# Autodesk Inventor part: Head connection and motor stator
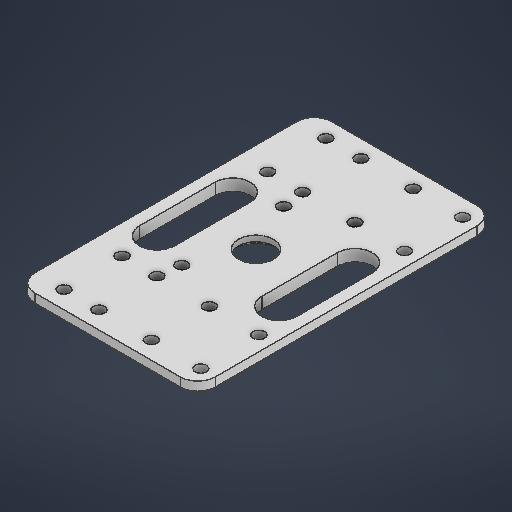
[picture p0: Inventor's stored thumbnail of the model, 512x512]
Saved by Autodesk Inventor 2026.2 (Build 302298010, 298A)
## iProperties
Created: 2026-05
Part Number: Head connection and motor stator
Material: 일반
Document SubType Name: Modeling
Designer: work
Density: 1 g/cm^3
Appearance: 기본값
Author: work
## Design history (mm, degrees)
sketch "스케치1"
  geometry: L1 (-9, 10)-(-26, 10); L2 (-26, 10)-(-26, -10); L3 (-26, -10)-(-9, -10); L4 (-9, -10)-(-9, 10); L5 (-9, 0)-(9, 0); L6 (21, 10)-(9, 10); L7 (9, 10)-(9, -10); L8 (9, -10)-(21, -10); L9 (21, -10)-(21, 10); L10 (-9, -80)-(-9, -60); L11 (-9, -60)-(-26, -60); L12 (-26, -60)-(-26, -80); L13 (-26, -80)-(-9, -80); L14 (-9, -70)-(9, -70); L15 (9, -60)-(9, -80); L16 (9, -80)-(21, -80); L17 (21, -60)-(9, -60); L18 (21, -80)-(21, -60); L19 (0, 0)-(0, -70); L20 (0, -35)-(8, -35); L21 (8, -17.5)-(8, -52.5); L22 (8, -17.5)-(43, -17.5); L23 (-31, 16)-(31, 16); L24 (31, 16)-(31, -86); L25 (31, -86)-(-31, -86); L26 (-31, -86)-(-31, 16); L27 (-31, 16)-(31, -86); L28 (31, 16)-(-31, -86); L29 (-27, -16)-(-15, -16); L30 (-15, -16)-(-15, -54); L31 (-15, -54)-(-27, -54); L32 (-27, -54)-(-27, -16); L33 (-27, -16)-(-15, -54); L34 (-15, -16)-(-27, -54); L35 (-31, -35)-(31, -35); L36 (31, -35)-(-31, -35); L37 (15, -16)-(15, -54); L38 (27, -54)-(27, -16); L39 (27, -16)-(15, -54); L40 (15, -16)-(27, -54); L41 (31, 16)-(-31, -86); L42 (-31, 16)-(31, -86); L43 (27, -16)-(15, -16); L44 (15, -54)-(27, -54); C1 r 2 at (21, 10); C2 r 2 at (9, 10); C3 r 2 at (9, -10); C4 r 2 at (21, -10); C5 r 2 at (-9, 10); C6 r 2 at (-9, -10); C7 r 2 at (-26, -10); C8 r 2 at (-26, 10); C9 r 2 at (-9, -60); C10 r 2 at (-9, -80); C11 r 2 at (-26, -60); C12 r 2 at (-26, -80); C13 r 2 at (9, -80); C14 r 2 at (9, -60); C15 r 2 at (21, -80); C16 r 2 at (21, -60); C17 r 6 at (0, -35); C18 r 2 at (8, -17.5); C19 r 2 at (8, -52.5); 13 further points
  constraints: 88 end point, 20 coincident, 19 centre point, 15 midpoint, 12 parallel, 11 symmetric about line, 10 horizontal, 8 perpendicular, 2 point on line, 1 vertical
  dimensions: "d0" = 20 distance of L3.end L1.start; "d1" = 18 distance of L5.end L5.start; "d2" = 17 distance of L2.end L3.end; "d3" = 12 distance of L8.end L7.end; "d4" = 20 distance of L7.end L6.end; "d5" = 4 diameter of C1; "d6" = 4 diameter of C2; "d7" = 4 diameter of C3; "d8" = 4 diameter of C4; "d9" = 4 diameter of C5; "d10" = 4 diameter of C6; "d11" = 4 diameter of C7; "d12" = 4 diameter of C8; "d13" = 20 distance of L10.start L10.end; "d14" = 18 distance of L14.end L14.start; "d15" = 17 distance of L12.end L10.start; "d16" = 12 distance of L16.end L15.end; "d17" = 20 distance of L15.end L15.start; "d18" = 4 diameter of C16; "d19" = 4 diameter of C14; "d20" = 4 diameter of C13; "d21" = 4 diameter of C15; "d22" = 4 diameter of C9; "d23" = 4 diameter of C10; "d24" = 4 diameter of C12; "d25" = 4 diameter of C11; "d26" = 70 distance of L19.start L19.end; "d27" = 12 diameter of C17; "d28" = 8 distance of L20.start L20.end; "d29" = 35 distance of L21.start L21.end; "d30" = 90 deg angle of L21 L22 (derived); "d31" = 4 diameter of C18; "d32" = 4 diameter of C19; "d33" = 10 distance between parallel lines of L24 L9; "d34" = 6 distance between parallel lines of L23 L6; "d35" = 6 distance from line of point (-17.5, -60) L31; "d36" = 4 distance between parallel lines of L26 L32; "d37" = 10 distance of L35.start point (-21, -35)
extrude "돌출1" new body sketch "스케치1" distance "d38" = 4; taper "d39" = 0 deg
fillet "모깎기1" dims "d40" = 6
chamfer "모따기1" distance "d41" = 2; stored, may be unused: second distance "d42" = 2, angle "d43" = 45 deg
chamfer "모따기2" distance "d44" = 1; stored, may be unused: second distance "d45" = 2, angle "d46" = 45 deg
feature "ǋ耀Ǎ耀Ǐ耀Ǒ耀Ǔ耀Ǖ耀Ǘ耀Ǚ耀" dims "d0" = 20, "d1" = 18, "d2" = 17, "d3" = 12, "d4" = 20, "d5" = 4, "d6" = 4, "d7" = 4, "d8" = 4, "d9" = 4, "d10" = 4, "d11" = 4, "d12" = 4, "d13" = 20, "d14" = 18, "d15" = 17, "d16" = 12, "d17" = 20, "d18" = 4, "d19" = 4, "d20" = 4, "d21" = 4, "d22" = 4, "d23" = 4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
node "솔리드1"
